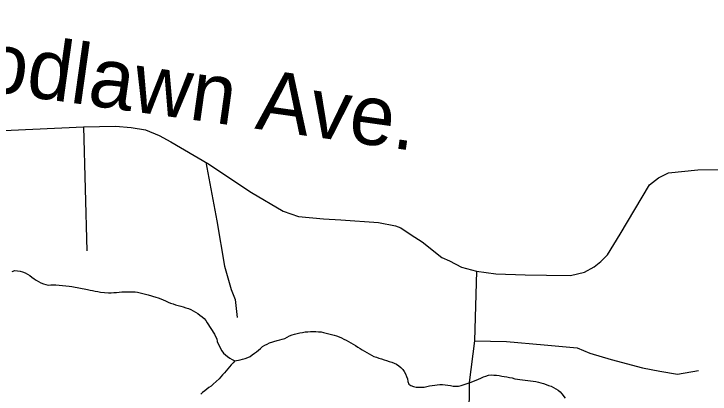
# Model space of a CAD drawing. Extents: x 1379448 to 1382868, y 593769 to 596827.
# Drawn here: x 1380109.7 to 1380281.1, y 595326.7 to 595420.3 of the extents above; entities that cross this region are included whole.
import ezdxf

# ---------------------------------------------------------------- set-up
doc = ezdxf.new("R2010")
doc.units = 0
for name, color, linetype in [('Old_Level_11', 7, 'Continuous'), ('Old_Level_32', 7, 'Continuous'), ('Old_Level_35', 7, 'Continuous'), ('Old_Level_59', 7, 'Continuous'), ('Old_Level_62', 7, 'Continuous')]:
    doc.layers.add(name, color=color, linetype=linetype)

msp = doc.modelspace()

# ---------------------------------------------------------------- linework, layer by layer
at = {"layer": 'Old_Level_32'}
msp.add_lwpolyline([(1380101.8, 595391.36), (1380126.8, 595392.46), (1380134.67, 595392.65), (1380138.53, 595392.33), (1380142.11, 595391.71), (1380145.43, 595390.31), (1380148.36, 595388.8), (1380157.45, 595383.48), (1380168.19, 595376.29), (1380176, 595371.7), (1380179.72, 595370.39), (1380185.9, 595369.84), (1380190.13, 595369.57), (1380199.44, 595368.97), (1380203.66, 595368.11), (1380204.95, 595367.64), (1380207.52, 595365.92), (1380210.18, 595364.18), (1380215, 595360.33), (1380216.91, 595359.53), (1380219.84, 595357.93), (1380223.58, 595356.98), (1380228.32, 595356.33), (1380235.51, 595356.08), (1380240.8, 595355.95), (1380246.72, 595355.92), (1380250.15, 595356.73), (1380252.56, 595358), (1380254.2, 595359.36), (1380255.83, 595360.96), (1380258.94, 595366.06), (1380266.13, 595378.18), (1380268.35, 595379.9), (1380270.85, 595381.12), (1380278.03, 595381.86), (1380283.86, 595382.01)], dxfattribs=at)
at = {"layer": 'Old_Level_35'}
for p, q in [((1380126.8, 595392.46), (1380127.61, 595361.97)), ((1380223.58, 595356.98), (1380223.05, 595339.83))]:
    msp.add_line(p, q, dxfattribs=at)
for points in [[(1380156.93, 595383.82), (1380159.61, 595369.37), (1380161.57, 595358.21), (1380163.17, 595352.42), (1380164.2, 595350.02), (1380164.64, 595345.57)], [(1380223.05, 595339.83), (1380221.79, 595329.56), (1380221.7, 595320.65), (1380222.43, 595315.97), (1380225.85, 595310.45), (1380231.64, 595301.68), (1380238.62, 595292.56), (1380240.66, 595287.3), (1380241.2, 595284.49), (1380241.39, 595276.99), (1380240.97, 595274.03)], [(1380223.05, 595339.83), (1380230.93, 595339.67), (1380240.26, 595338.82), (1380248.34, 595338.12), (1380251.42, 595336.74), (1380256.67, 595335.2), (1380264.43, 595333.19), (1380268.66, 595332.33), (1380273.04, 595331.63), (1380278.21, 595332.49)]]:
    msp.add_lwpolyline(points, dxfattribs=at)
at = {"layer": 'Old_Level_59'}
for points in [[(1380109.28, 595356.89), (1380109.9, 595357.1), (1380110.56, 595357.05), (1380111.21, 595356.94), (1380111.84, 595356.77), (1380112.45, 595356.52), (1380113.03, 595356.21), (1380113.58, 595355.85), (1380114.12, 595355.47), (1380114.66, 595355.09), (1380115.2, 595354.73), (1380115.76, 595354.38), (1380116.34, 595354.07), (1380116.95, 595353.84), (1380117.59, 595353.68), (1380118.23, 595353.53), (1380118.8, 595353.62), (1380120.02, 595353.56), (1380123.29, 595353.27), (1380123.94, 595353.17), (1380127.8, 595352.43), (1380128.44, 595352.31), (1380129.08, 595352.18), (1380129.73, 595352.05), (1380130.37, 595351.93), (1380131.02, 595351.82), (1380132.96, 595351.65), (1380133.62, 595351.66), (1380134.28, 595351.67), (1380134.93, 595351.7), (1380135.59, 595351.76), (1380136.23, 595351.86)], [(1380136.23, 595351.86), (1380136.88, 595351.88), (1380137.54, 595351.89), (1380138.21, 595351.89), (1380138.87, 595351.88), (1380139.51, 595351.83), (1380140.16, 595351.75), (1380140.8, 595351.63), (1380141.44, 595351.48), (1380142.08, 595351.32), (1380142.71, 595351.13), (1380144.61, 595350.58), (1380145.24, 595350.39), (1380145.86, 595350.17), (1380146.47, 595349.92), (1380147.04, 595349.62), (1380147.64, 595349.33), (1380148.25, 595349.1), (1380148.87, 595348.9), (1380149.5, 595348.7), (1380150.13, 595348.52), (1380150.76, 595348.33), (1380151.39, 595348.15), (1380152.02, 595347.95), (1380152.64, 595347.75), (1380153.26, 595347.52), (1380153.85, 595347.23), (1380154.42, 595346.9), (1380154.96, 595346.54), (1380155.5, 595346.16), (1380156.02, 595345.75), (1380156.5, 595345.31), (1380156.94, 595344.82), (1380157.31, 595344.28), (1380159.04, 595341.49), (1380159.34, 595340.91), (1380159.61, 595340.31), (1380159.74, 595339.67), (1380160.01, 595339.07), (1380160.29, 595338.47), (1380160.58, 595337.89), (1380160.91, 595337.32), (1380161.31, 595336.8), (1380161.77, 595336.33), (1380162.29, 595335.92), (1380162.84, 595335.57), (1380163.42, 595335.25), (1380164.06, 595334.9)], [(1380164.06, 595334.9), (1380165.36, 595335.13), (1380165.99, 595335.27), (1380166.63, 595335.46), (1380167.24, 595335.7), (1380167.82, 595335.99), (1380168.37, 595336.36), (1380168.9, 595336.74), (1380169.42, 595337.14), (1380170.43, 595337.93), (1380170.9, 595338.4), (1380171.46, 595338.72), (1380172.06, 595339.02), (1380172.65, 595339.28), (1380174.49, 595339.92), (1380175.13, 595340.06), (1380175.77, 595340.21), (1380176.4, 595340.4), (1380176.99, 595340.68), (1380177.57, 595341.01), (1380178.17, 595341.26), (1380178.79, 595341.45), (1380179.43, 595341.61), (1380180.07, 595341.75), (1380180.72, 595341.89), (1380181.36, 595342), (1380182.02, 595342.05), (1380182.68, 595342.08), (1380183.33, 595342.09), (1380183.99, 595342.09), (1380184.65, 595342.06), (1380185.3, 595341.99), (1380185.94, 595341.88), (1380186.58, 595341.73), (1380187.23, 595341.57), (1380187.86, 595341.4), (1380188.5, 595341.23), (1380189.12, 595341.02), (1380189.73, 595340.79), (1380190.33, 595340.53), (1380190.92, 595340.25), (1380191.5, 595339.94), (1380192.08, 595339.63), (1380192.66, 595339.3), (1380193.22, 595338.97), (1380193.78, 595338.63), (1380194.34, 595338.28), (1380194.89, 595337.93), (1380195.45, 595337.58), (1380196.01, 595337.24), (1380196.57, 595336.91), (1380197.15, 595336.58), (1380197.72, 595336.27), (1380198.32, 595335.99), (1380198.93, 595335.76), (1380199.55, 595335.54), (1380200.18, 595335.34), (1380200.81, 595335.15), (1380201.44, 595334.95), (1380202.07, 595334.75), (1380202.69, 595334.54), (1380203.3, 595334.31), (1380203.89, 595334.03), (1380204.43, 595333.66), (1380204.95, 595333.26), (1380205.41, 595332.79), (1380205.78, 595332.24), (1380206.08, 595331.66), (1380206.36, 595331.06), (1380206.6, 595330.45), (1380206.69, 595329.8), (1380206.92, 595329.18), (1380207.44, 595328.82), (1380208.07, 595328.58), (1380208.72, 595328.43), (1380209.38, 595328.37), (1380210.04, 595328.37), (1380210.69, 595328.42), (1380211.34, 595328.54), (1380211.97, 595328.71), (1380212.62, 595328.84), (1380214.55, 595329.03), (1380215.21, 595329.05), (1380215.86, 595328.98), (1380216.51, 595328.88), (1380217.16, 595328.78), (1380217.81, 595328.69), (1380218.47, 595328.63), (1380219.12, 595328.67), (1380219.75, 595328.85), (1380222.25, 595329.66), (1380224.06, 595330.35), (1380224.66, 595330.64), (1380225.26, 595330.91), (1380225.87, 595331.14), (1380226.5, 595331.33), (1380227.16, 595331.42), (1380227.81, 595331.4), (1380228.46, 595331.33), (1380229.11, 595331.25)], [(1380229.11, 595331.25), (1380229.76, 595331.15), (1380230.41, 595331.04), (1380231.06, 595330.92), (1380231.71, 595330.8), (1380232.35, 595330.68), (1380232.98, 595330.49), (1380234.9, 595330.17), (1380235.56, 595330.12), (1380236.21, 595330.06), (1380236.87, 595330), (1380237.52, 595329.91), (1380238.16, 595329.78), (1380238.79, 595329.63), (1380239.43, 595329.46), (1380240.05, 595329.27), (1380240.68, 595329.06), (1380241.31, 595328.85), (1380241.92, 595328.63), (1380242.52, 595328.36), (1380243.09, 595328.02), (1380243.63, 595327.64), (1380244.14, 595327.23), (1380244.56, 595326.74), (1380245.35, 595325.71)]]:
    msp.add_lwpolyline(points, dxfattribs=at)
at = {"layer": 'Old_Level_62'}
msp.add_lwpolyline([(1380164.06, 595334.9), (1380163.63, 595334.4), (1380163.2, 595333.9), (1380162.78, 595333.4), (1380162.35, 595332.91), (1380161.92, 595332.41), (1380161.5, 595331.91), (1380161.06, 595331.41), (1380160.63, 595330.92), (1380160.2, 595330.44), (1380158.75, 595329.12), (1380158.25, 595328.69), (1380157.72, 595328.3), (1380157.19, 595327.92), (1380156.66, 595327.53), (1380156.16, 595327.1), (1380155.69, 595326.65)], dxfattribs=at)

# ---------------------------------------------------------------- texts
at = {"layer": 'Old_Level_11'}
msp.add_text('Woodlawn Ave.', height=14.7638, rotation=351.9985, dxfattribs=at).set_placement((1380072.12, 595405.66))

doc.saveas('drawing.dxf')
